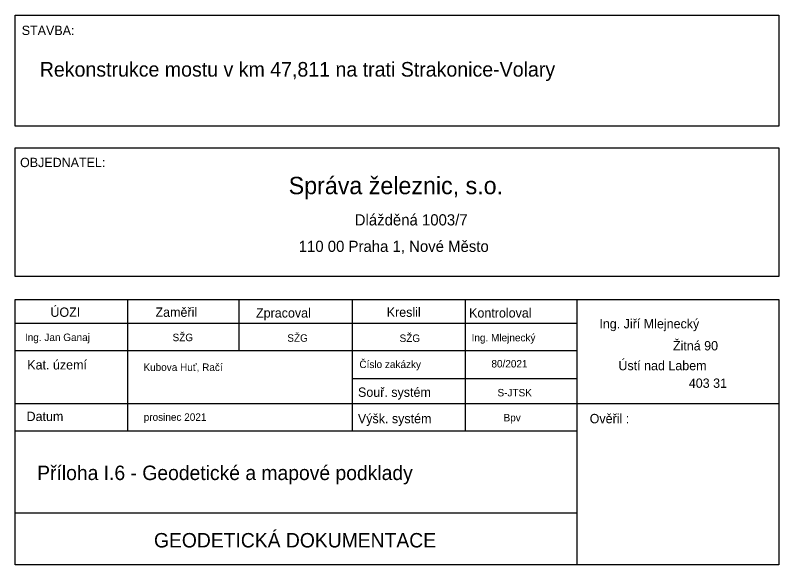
# Model space of a CAD drawing. Extents: x -879530 to -879371, y -1019242 to -1019127.
import ezdxf

# ---------------------------------------------------------------- set-up
doc = ezdxf.new("R2010")
doc.units = 0
doc.layers.add('tabulka', color=7, linetype='Continuous')

msp = doc.modelspace()

# ---------------------------------------------------------------- linework, layer by layer
at = {"layer": 'tabulka'}
for p, q in [((-879530.09, -1019186.45), (-879371.44, -1019186.45)), ((-879506.8, -1019186.45), (-879506.8, -1019213.77)), ((-879483.66, -1019186.45), (-879483.66, -1019197.07)), ((-879460.06, -1019186.45), (-879460.06, -1019213.77)), ((-879436.61, -1019186.45), (-879436.61, -1019213.77)), ((-879413.31, -1019241.58), (-879413.31, -1019186.45)), ((-879530.09, -1019191.36), (-879413.31, -1019191.36)), ((-879530.09, -1019197.07), (-879413.31, -1019197.07)), ((-879460.06, -1019202.88), (-879413.31, -1019202.88)), ((-879530.09, -1019208.07), (-879371.44, -1019208.07)), ((-879530.09, -1019213.77), (-879413.31, -1019213.77)), ((-879530.09, -1019230.76), (-879413.31, -1019230.76))]:
    msp.add_line(p, q, dxfattribs=at)
for points in [[(-879530.09, -1019127.36), (-879371.44, -1019127.36), (-879371.44, -1019150.43), (-879530.09, -1019150.43)], [(-879530.09, -1019154.95), (-879371.44, -1019154.95), (-879371.44, -1019181.64), (-879530.09, -1019181.64)]]:
    msp.add_lwpolyline(points, close=True, dxfattribs=at)
msp.add_lwpolyline([(-879371.44, -1019186.45), (-879371.44, -1019241.58), (-879530.09, -1019241.58), (-879530.09, -1019186.45)], dxfattribs=at)

# ---------------------------------------------------------------- texts
for s, height, p in [('STAVBA:', 1.94, (-879528.75, -1019131.47)), ('Rekonstrukce mostu v km 47,811 na trati Strakonice-Volary', 3.04, (-879525, -1019140.12)), ('OBJEDNATEL:', 1.94, (-879529.1, -1019158.93)), ('Správa železnic, s.o.', 3.61, (-879473.27, -1019164.56)), ('Dlážděná 1003/7', 2.32, (-879459.55, -1019171.05)), ('110 00 Praha 1, Nové Město', 2.32, (-879471.19, -1019176.55)), ('ÚOZI', 1.94, (-879522.79, -1019190.05)), ('Zaměřil', 1.94, (-879500.95, -1019190.05)), ('Zpracoval', 1.94, (-879480.06, -1019190.2)), ('Kreslil', 1.94, (-879452.9, -1019190.05)), ('Kontroloval', 1.94, (-879435.78, -1019190.2)), ('Ing. Jiří Mlejnecký', 1.94, (-879408.71, -1019192.45)), ('Ing. Jan Ganaj', 1.552, (-879528.08, -1019195.08)), ('SŽG', 1.552, (-879497.41, -1019195.11)), ('SŽG', 1.552, (-879473.56, -1019195.23)), ('SŽG', 1.552, (-879450.23, -1019195.27)), ('Ing. Mlejnecký', 1.552, (-879435.26, -1019195.15)), ('Žitná 90', 1.94, (-879393.42, -1019197.03)), ('Kat. území', 1.94, (-879527.6, -1019200.99)), ('Kubova Huť, Račí', 1.552, (-879503.46, -1019201.3)), ('Číslo zakázky', 1.552, (-879458.58, -1019200.7)), ('80/2021', 1.552, (-879431.14, -1019200.58)), ('Ústí nad Labem', 1.94, (-879404.75, -1019201.15)), ('403 31', 1.94, (-879390.12, -1019204.81)), ('Souř. systém', 1.94, (-879458.87, -1019206.68)), ('S-JTSK', 1.552, (-879429.88, -1019206.59)), ('Datum', 1.94, (-879527.74, -1019211.71)), ('prosinec 2021', 1.552, (-879503.4, -1019211.67)), ('Výšk. systém', 1.94, (-879458.89, -1019212.17)), ('Bpv', 1.552, (-879428.62, -1019211.78)), ('Ověřil :', 1.94, (-879410.72, -1019212.17)), ('Příloha I.6 - Geodetické a mapové podklady', 3, (-879525.54, -1019223.98)), ('GEODETICKÁ DOKUMENTACE ', 3, (-879501.27, -1019237.99))]:
    msp.add_text(s, height=height, dxfattribs=at).set_placement(p)

doc.saveas('drawing.dxf')
